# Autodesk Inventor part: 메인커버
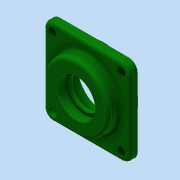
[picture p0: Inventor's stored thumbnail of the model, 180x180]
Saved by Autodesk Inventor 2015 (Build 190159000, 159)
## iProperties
Created: 2018-09
Part Number: 메인커버
Material: 알루미늄 6061
Document SubType Name: Modeling
Designer: mduedu
Density: 2.71 g/cm^3
Appearance: 진녹색
Mass: 178.463 g
Surface Area: 197.883 cm^2
Volume: 65.8536 cm^3
Author: mduedu
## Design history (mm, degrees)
sketch "스케치1"
  geometry: L1 (-40, -40)-(40, -40); L2 (40, -40)-(40, 40); L3 (40, 40)-(-40, 40); L4 (-40, 40)-(-40, -40); L5 (-40, -40)-(40, 40); L6 (40, -40)-(-40, 40); 1 further point
  constraints: 12 end point, 2 midpoint, 2 parallel, 1 horizontal, 1 perpendicular
  dimensions: "d0" = 80 distance of L3.end L2.end; "d1" = 80 distance of L2.end L1.end
extrude "돌출1" new body sketch "스케치1" distance "d2" = 7; taper "d3" = 0 deg
sketch "스케치2"
  geometry: C1 r 30 at (0, 0); 1 further point
  constraints: 1 centre point, 1 coincident
  dimensions: "d4" = 60 diameter of C1
extrude "돌출2" join sketch "스케치2" distance "d5" = 10; taper "d6" = 0 deg
sketch "스케치3"
  geometry: C1 r 32.5 at (0, 0); 1 further point
  constraints: 1 centre point, 1 coincident
  dimensions: "d7" = 65 diameter of C1
extrude "돌출3" join sketch "스케치3" distance "d8" = 9; taper "d9" = 0 deg
sketch "스케치4"
  geometry: L1 (-32.5, -9)-(32.5, -9) reference; L2 (30, 17)-(-30, 17) reference; L3 (0, 17)-(0, -9); L4 (0, -9)-(23.5, -9); L5 (23.5, -9)-(23.5, 5); L6 (23.5, 5)-(0, 5); L7 (0, 5)-(0, -9); L8 (0, 5)-(15, 5); L9 (15, 5)-(15, 8.7); L10 (15, 8.7)-(0, 8.7); L11 (0, 8.7)-(0, 5); L12 (0, 8.7)-(17.5, 8.7); L13 (17.5, 8.7)-(17.5, 17); L14 (17.5, 17)-(0, 17); L15 (0, 17)-(0, 8.7); 1 further point
  constraints: 26 end point, 6 parallel, 3 horizontal, 3 perpendicular, 2 midpoint, 1 point on line
  dimensions: "d10" = 14 distance of L4.end L5.end; "d12" = 8.3 distance of L12.end L13.end; "d13" = 35 diameter of L13 L3; "d14" = 30 diameter of L9 L3; "d15" = 47 diameter of L5 L3
revolve "회전1" sketch "스케치4" stored, may be unused: angle "d16" = 90 deg
fillet "모깎기1" dims "d17" = 8
fillet "모깎기2" dims "d18" = 3
fillet "모깎기3" dims "d19" = 3
chamfer "모따기1" distance "d20" = 0.8; stored, may be unused: second distance "d21" = 2, angle "d22" = 30 deg
chamfer "모따기2" distance "d23" = 1; stored, may be unused: second distance "d24" = 2, angle "d25" = 30 deg
fillet "모깎기4" dims "d26" = 0.3
sketch "스케치5"
  geometry: A1 r 8 centre (-32, 32) between (-32, 40) and (-40, 32) reference; A2 r 8 centre (-32, -32) between (-40, -32) and (-32, -40) reference; A3 r 8 centre (32, -32) between (32, -40) and (40, -32) reference; A4 r 8 centre (32, 32) between (40, 32) and (32, 40) reference; 5 further points
  constraints: 4 coincident
hole "구멍1" sketch "스케치5" at (-32, 32), (32, 32), (32, -32), (-32, -32) diameter "d27" = 4.5; stored, may be unused: countersink angle "d31" = 90 deg, drill point angle "d33" = 118 deg; dims "d28" = 6, "d29" = 8, "d30" = 4.4, "d32" = 8
node "솔리드1"
